(* Logix 5000 project; controller AMCI_3601_AOP_AOI_Sample_RSLogix_V28 vendor 1 type 14 code 108 rev 28.11; software revision 28.00; part 4 of 4 *)

ADD_ON_INSTRUCTION AMCI_3601_AOP_Relative_Move   (* revision 0.0, vendor AMCI, ExecuteEnableInFalse *)
// Revision note:
// 3/2020: Version 0 is the initial release
VAR_INPUT
   Axis_Status_Bits : INT; {required}
   _0_normal_1_S_Curve_Acceleration : BOOL;
   _0_Triangular_1_Trapezoidal_S_Curve : BOOL;
   _0_Target_Move_1_Encoder_Move : BOOL;
   Target_Position : DINT; {required}
   Programmed_Speed : DINT; {required}
   Acceleration : INT; {required}
   Deceleration : INT; {required}
END_VAR
VAR_OUTPUT
   EN : BOOL; {access Read Only, visible}
   ER : BOOL; {access Read Only, visible}
END_VAR
VAR_IN_OUT
   AMCI_3601_output_data : AM:1769_3601:O:0; {required}
END_VAR
VAR
   Upper_Result_X_1000 : DINT;
   command_data_block : INT[10];
        [1]   // Command Bits LSW
        [3]   // Lower Target Position
        [5]   // Lower Programmed Speed
        [0]   // Command Bits MSW
        [2]   // Upper Target Position
        [4]   // Upper Programmed Speed
END_VAR

ROUTINE EnableInFalse   (* ladder *)
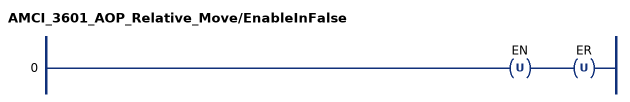
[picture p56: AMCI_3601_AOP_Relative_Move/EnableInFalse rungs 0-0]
   0: OTU(EN)OTU(ER);
END_ROUTINE

ROUTINE Logic   (* ladder *)
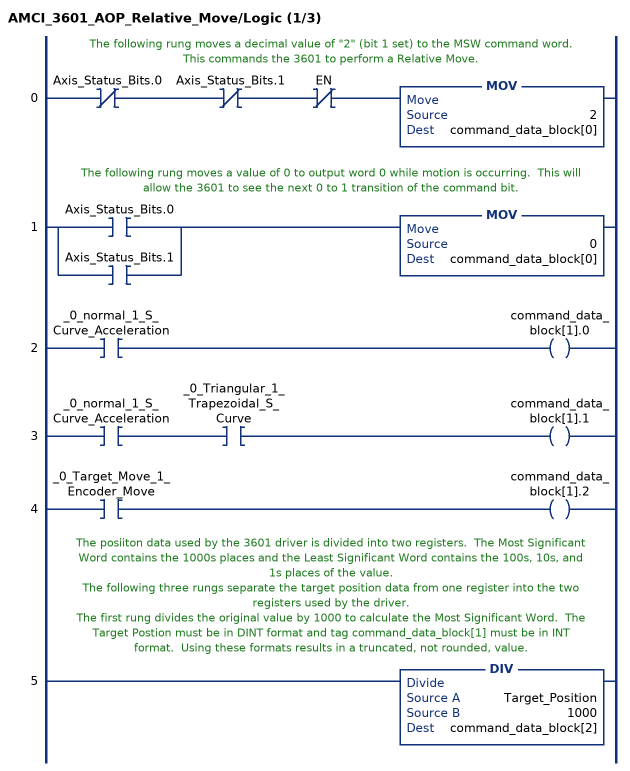
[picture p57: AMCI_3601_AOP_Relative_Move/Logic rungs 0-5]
   // The following rung moves a decimal value of "2" (bit 1 set) to the MSW command word.  This commands the 3601 to perform a Relative Move.
   0: XIO(Axis_Status_Bits.0)XIO(Axis_Status_Bits.1)XIO(EN)MOV(2,command_data_block[0]);
   // The following rung moves a value of 0 to output word 0 while motion is occurring.  This will allow the 3601 to see the next 0 to 1 transition of the command bit.
   1: [XIC(Axis_Status_Bits.0) ,XIC(Axis_Status_Bits.1) ]MOV(0,command_data_block[0]);
   2: XIC(_0_normal_1_S_Curve_Acceleration)OTE(command_data_block[1].0);
   3: XIC(_0_normal_1_S_Curve_Acceleration)XIC(_0_Triangular_1_Trapezoidal_S_Curve)OTE(command_data_block[1].1);
   4: XIC(_0_Target_Move_1_Encoder_Move)OTE(command_data_block[1].2);
   // The posiiton data used by the 3601 driver is divided into two registers.  The Most Significant Word contains the 1000s places and the Least Significant Word contains the 100s, 10s, and 1s places of the value.
   // The following three rungs separate the target position data from one register into the two registers used by the driver.
   // The first rung divides the original value by 1000 to calculate the Most Significant Word.  The Target Postion must be in DINT format and tag command_data_block[1] must be in INT format.  Using these formats results in a truncated, not rounded, value.
   5: DIV(Target_Position,1000,command_data_block[2]);
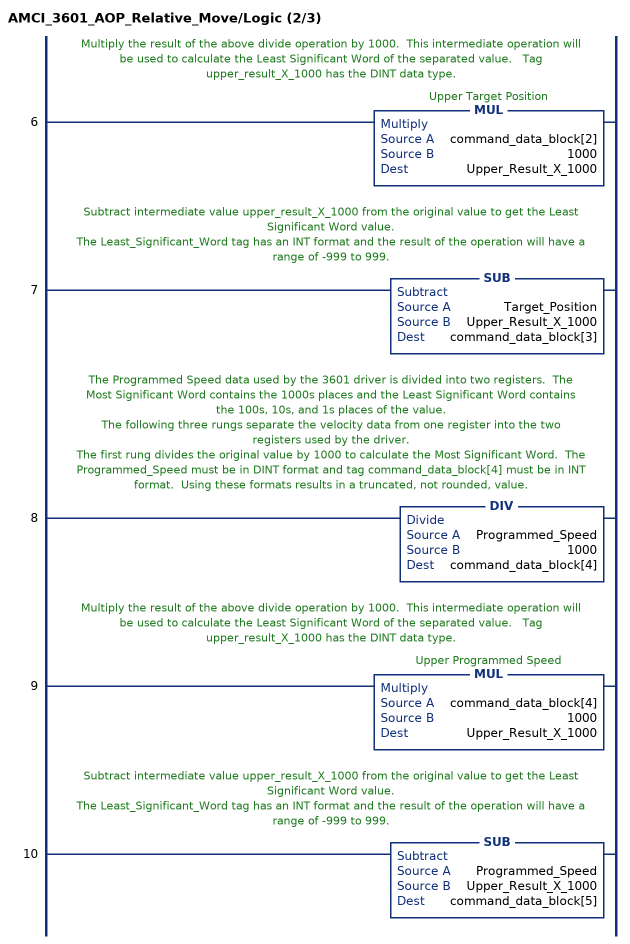
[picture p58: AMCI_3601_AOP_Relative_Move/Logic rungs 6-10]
   // Multiply the result of the above divide operation by 1000.  This intermediate operation will be used to calculate the Least Significant Word of the separated value.   Tag upper_result_X_1000 has the DINT data type.
   6: MUL(command_data_block[2],1000,Upper_Result_X_1000);
   // Subtract intermediate value upper_result_X_1000 from the original value to get the Least Significant Word value.
   // The Least_Significant_Word tag has an INT format and the result of the operation will have a range of -999 to 999.
   7: SUB(Target_Position,Upper_Result_X_1000,command_data_block[3]);
   // The Programmed Speed data used by the 3601 driver is divided into two registers.  The Most Significant Word contains the 1000s places and the Least Significant Word contains the 100s, 10s, and 1s places of the value.
   // The following three rungs separate the velocity data from one register into the two registers used by the driver.
   // The first rung divides the original value by 1000 to calculate the Most Significant Word.  The Programmed_Speed must be in DINT format and tag command_data_block[4] must be in INT format.  Using these formats results in a truncated, not rounded, value.
   8: DIV(Programmed_Speed,1000,command_data_block[4]);
   // Multiply the result of the above divide operation by 1000.  This intermediate operation will be used to calculate the Least Significant Word of the separated value.   Tag upper_result_X_1000 has the DINT data type.
   9: MUL(command_data_block[4],1000,Upper_Result_X_1000);
   // Subtract intermediate value upper_result_X_1000 from the original value to get the Least Significant Word value.
   // The Least_Significant_Word tag has an INT format and the result of the operation will have a range of -999 to 999.
   10: SUB(Programmed_Speed,Upper_Result_X_1000,command_data_block[5]);
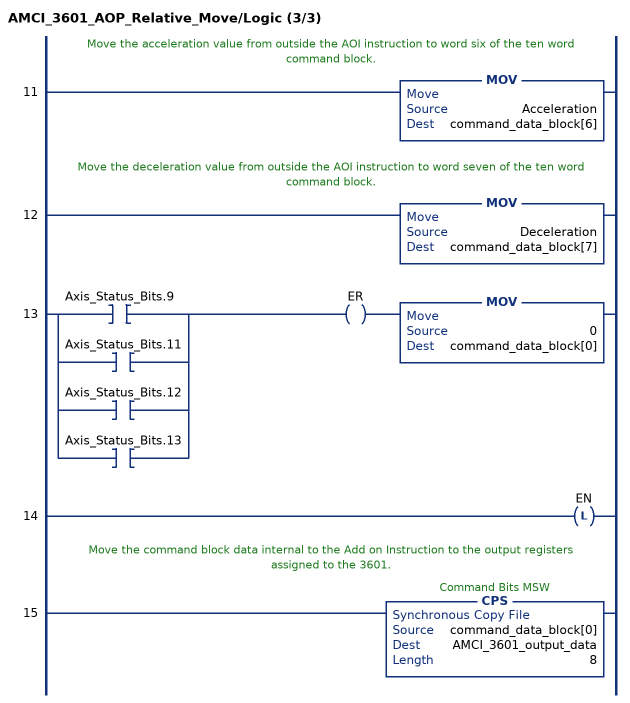
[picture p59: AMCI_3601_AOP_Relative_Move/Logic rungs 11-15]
   // Move the acceleration value from outside the AOI instruction to word six of the ten word command block.
   11: MOV(Acceleration,command_data_block[6]);
   // Move the deceleration value from outside the AOI instruction to word seven of the ten word command block.
   12: MOV(Deceleration,command_data_block[7]);
   13: [XIC(Axis_Status_Bits.9) ,XIC(Axis_Status_Bits.11) ,XIC(Axis_Status_Bits.12) ,XIC(Axis_Status_Bits.13) ]OTE(ER)MOV(0,command_data_block[0]);
   14: OTL(EN);
   // Move the command block data internal to the Add on Instruction to the output registers assigned to the 3601.
   15: CPS(command_data_block[0],AMCI_3601_output_data,8);
END_ROUTINE
END_ADD_ON_INSTRUCTION

ADD_ON_INSTRUCTION AMCI_3601_AOP_Reset_Errors   (* revision 0.0, vendor AMCI, ExecuteEnableInFalse *)
// Revision note:
// 3/2020: Version 0 is the initial release
VAR_INPUT
   Axis_Status_Bits : INT; {required}
END_VAR
VAR_OUTPUT
   EN : BOOL; {access Read Only, visible}
   ER : BOOL; {access Read Only, visible}
END_VAR
VAR_IN_OUT
   AMCI_3601_output_data : AM:1769_3601:O:0; {required}
END_VAR
VAR
   Upper_Result_X_1000 : DINT;
   command_data_block : INT[10];
        [1]   // Command Bits LSW
        [3]   // Lower Target Position
        [5]   // Lower Programmed Speed
        [0]   // Command Bits MSW
        [2]   // Upper Target Position
        [4]   // Upper Programmed Speed
END_VAR

ROUTINE EnableInFalse   (* ladder *)
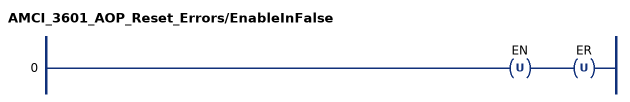
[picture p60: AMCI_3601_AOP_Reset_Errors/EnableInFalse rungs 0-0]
   0: OTU(EN)OTU(ER);
END_ROUTINE

ROUTINE Logic   (* ladder *)
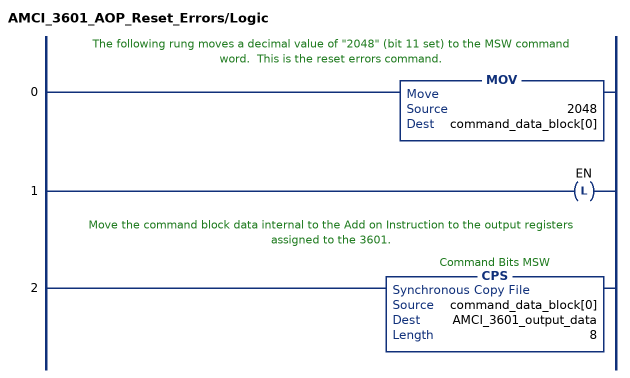
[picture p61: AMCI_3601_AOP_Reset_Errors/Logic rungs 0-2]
   // The following rung moves a decimal value of "2048" (bit 11 set) to the MSW command word.  This is the reset errors command.
   0: MOV(2048,command_data_block[0]);
   1: OTL(EN);
   // Move the command block data internal to the Add on Instruction to the output registers assigned to the 3601.
   2: CPS(command_data_block[0],AMCI_3601_output_data,8);
END_ROUTINE
END_ADD_ON_INSTRUCTION

ADD_ON_INSTRUCTION AMCI_3601_AOP_Resume   (* revision 0.0, vendor AMCI, ExecuteEnableInFalse *)
// Revision note:
// 3/2020: Version 0 is the initial release
VAR_INPUT
   Axis_Status_Bits : INT; {required}
END_VAR
VAR_OUTPUT
   EN : BOOL; {access Read Only, visible}
   ER : BOOL; {access Read Only, visible}
END_VAR
VAR_IN_OUT
   AMCI_3601_output_data : AM:1769_3601:O:0; {required}
END_VAR
VAR
   Upper_Result_X_1000 : DINT;
   command_data_block : INT[10];
        [1]   // Command Bits LSW
        [3]   // Lower Target Position
        [5]   // Lower Programmed Speed
        [0]   // Command Bits MSW
        [2]   // Upper Target Position
        [4]   // Upper Programmed Speed
END_VAR

ROUTINE EnableInFalse   (* ladder *)
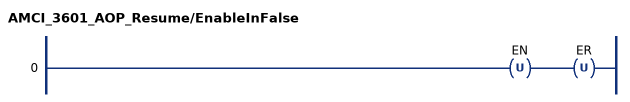
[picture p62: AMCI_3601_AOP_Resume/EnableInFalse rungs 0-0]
   0: OTU(EN)OTU(ER);
END_ROUTINE

ROUTINE Logic   (* ladder *)
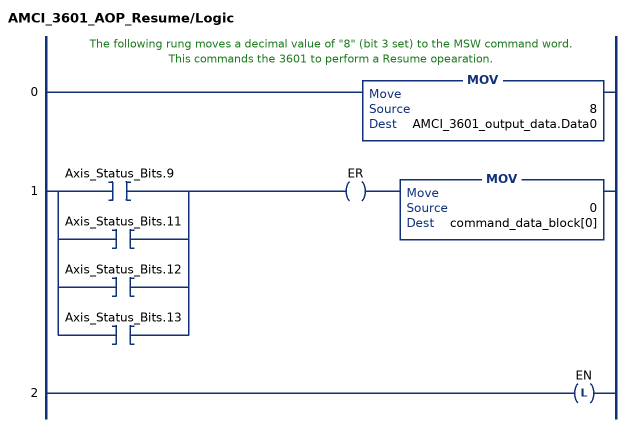
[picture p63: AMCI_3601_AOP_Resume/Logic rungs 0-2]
   // The following rung moves a decimal value of "8" (bit 3 set) to the MSW command word.  This commands the 3601 to perform a Resume opearation.
   0: MOV(8,AMCI_3601_output_data.Data0);
   1: [XIC(Axis_Status_Bits.9) ,XIC(Axis_Status_Bits.11) ,XIC(Axis_Status_Bits.12) ,XIC(Axis_Status_Bits.13) ]OTE(ER)MOV(0,command_data_block[0]);
   2: OTL(EN);
END_ROUTINE
END_ADD_ON_INSTRUCTION

ADD_ON_INSTRUCTION AMCI_3601_AOP_Run_Blend   (* revision 0.0, vendor AMCI, ExecuteEnableInFalse *)
// Revision note:
// 3/2020: Version 0 is the initial release
VAR_INPUT
   Axis_Status_Bits : INT; {required}
   Direction_0_Positive_1_Negative : BOOL; {required}
END_VAR
VAR_OUTPUT
   EN : BOOL; {access Read Only, visible}
   ER : BOOL; {access Read Only, visible}
END_VAR
VAR_IN_OUT
   AMCI_3601_output_data : AM:1769_3601:O:0; {required}
END_VAR
VAR
   Upper_Result_X_1000 : DINT;
   command_data_block : INT[10];
        [1]   // Command Bits LSW
        [3]   // Lower Target Position
        [5]   // Lower Programmed Speed
        [0]   // Command Bits MSW
        [2]   // Upper Target Position
        [4]   // Upper Programmed Speed
END_VAR

ROUTINE EnableInFalse   (* ladder *)
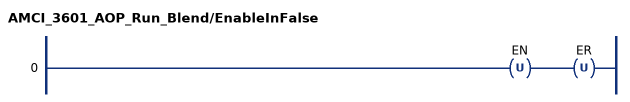
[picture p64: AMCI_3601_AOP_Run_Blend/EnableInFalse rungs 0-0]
   0: OTU(EN)OTU(ER);
END_ROUTINE

ROUTINE Logic   (* ladder *)
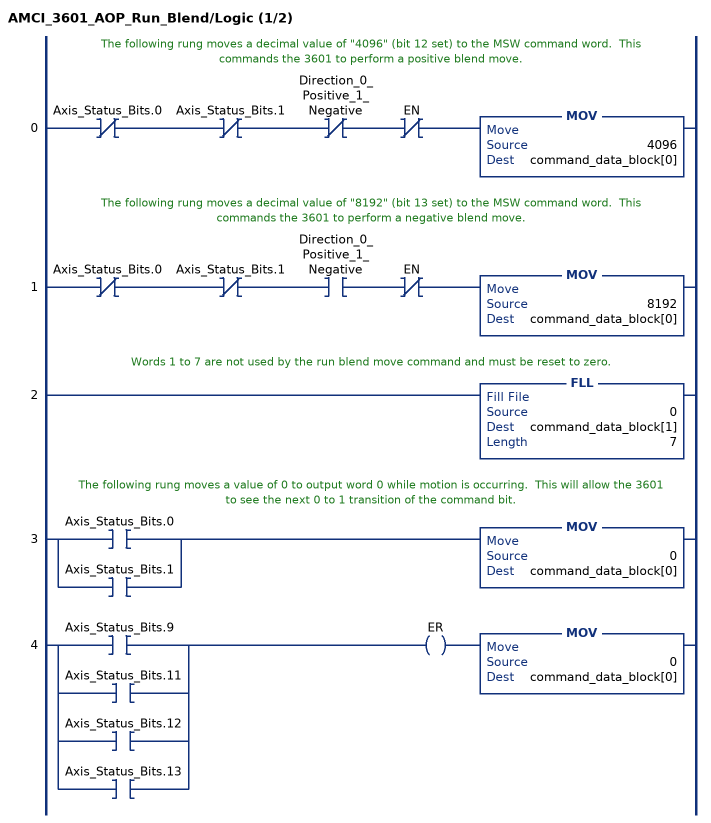
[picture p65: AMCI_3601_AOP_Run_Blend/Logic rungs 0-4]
   // The following rung moves a decimal value of "4096" (bit 12 set) to the MSW command word.  This commands the 3601 to perform a positive blend move.
   0: XIO(Axis_Status_Bits.0)XIO(Axis_Status_Bits.1)XIO(Direction_0_Positive_1_Negative)XIO(EN)MOV(4096,command_data_block[0]);
   // The following rung moves a decimal value of "8192" (bit 13 set) to the MSW command word.  This commands the 3601 to perform a negative blend move.
   1: XIO(Axis_Status_Bits.0)XIO(Axis_Status_Bits.1)XIC(Direction_0_Positive_1_Negative)XIO(EN)MOV(8192,command_data_block[0]);
   // Words 1 to 7 are not used by the run blend move command and must be reset to zero.
   2: FLL(0,command_data_block[1],7);
   // The following rung moves a value of 0 to output word 0 while motion is occurring.  This will allow the 3601 to see the next 0 to 1 transition of the command bit.
   3: [XIC(Axis_Status_Bits.0) ,XIC(Axis_Status_Bits.1) ]MOV(0,command_data_block[0]);
   4: [XIC(Axis_Status_Bits.9) ,XIC(Axis_Status_Bits.11) ,XIC(Axis_Status_Bits.12) ,XIC(Axis_Status_Bits.13) ]OTE(ER)MOV(0,command_data_block[0]);
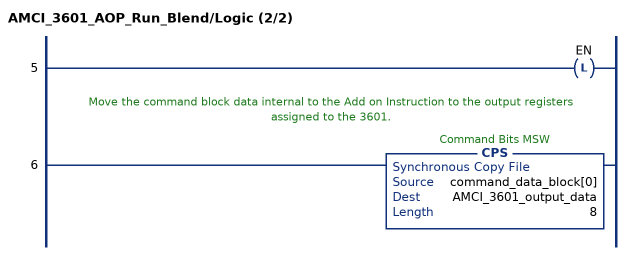
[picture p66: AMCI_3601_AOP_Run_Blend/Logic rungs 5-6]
   5: OTL(EN);
   // Move the command block data internal to the Add on Instruction to the output registers assigned to the 3601.
   6: CPS(command_data_block[0],AMCI_3601_output_data,8);
END_ROUTINE
END_ADD_ON_INSTRUCTION

VAR_GLOBAL   (* controller tags *)
   buffered_3601_data : INT[8];
        [0].13   // set when configuration error
        [0].15   // 3601 mode 0=command 1=configuration
   comment_coil : INT;
   run_3601 : DINT;   // 1=relative move 2=CW Manual Move 3=CCW Manual Move 4=Home CW 5=Reset Errors 6=Preset 7=Program Blend 8=Run Blend
END_VAR

PROGRAM MainProgram   (* main routine MainRoutine *)
VAR
   AMCI_3601_absolute_move_AOI : AMCI_3601_AOP_Absolute_Move;
   AMCI_3601_Config_AOI : AMCI_3601_AOP_Configure;
   AMCI_3601_encoder_follower_AOI : AMCI_3601_AOP_Encoder_Follower;
   AMCI_3601_Hold_AOI : AMCI_3601_AOP_Hold;
   AMCI_3601_Home_CCW_AOI : AMCI_3601_AOP_Home_CCW;
   AMCI_3601_Home_CW_AOI : AMCI_3601_AOP_Home_CW;
   AMCI_3601_Immediate_Stop_AOI : AMCI_3601_AOP_Immediate_Stop;
   AMCI_3601_Manual_Move_CCW_AOI : AMCI_3601_AOP_Manual_Move_CCW;
   AMCi_3601_Manual_Move_CW_AOI : AMCI_3601_AOP_Manual_Move_CW;
   AMCI_3601_Preset_AOI : AMCI_3601_AOP_Preset;
   AMCI_3601_Preset_Encoder_AOI : AMCI_3601_AOP_Preset_Encoder;
   AMCI_3601_program_blend_AOI : AMCI_3601_AOP_Program_Blend_Move;
   AMCI_3601_Registration_CCW : AMCI_3601_AOP_Registration_CCW;
   AMCI_3601_Registration_CW_AOI : AMCI_3601_AOP_Registration_CW;
   AMCI_3601_Relative_Move_AOI : AMCI_3601_AOP_Relative_Move;
   AMCI_3601_Reset_Error_AOI : AMCI_3601_AOP_Reset_Errors;
   AMCI_3601_Resume_AOI : AMCI_3601_AOP_Resume;
   AMCI_3601_run_blend_AOI : AMCI_3601_AOP_Run_Blend;
   AMCI_Prog_Min_Registration_Distance_AOI : AMCI_3601_AOP_Min_Registration_Distance;
END_VAR

ROUTINE MainRoutine   (* ladder *)
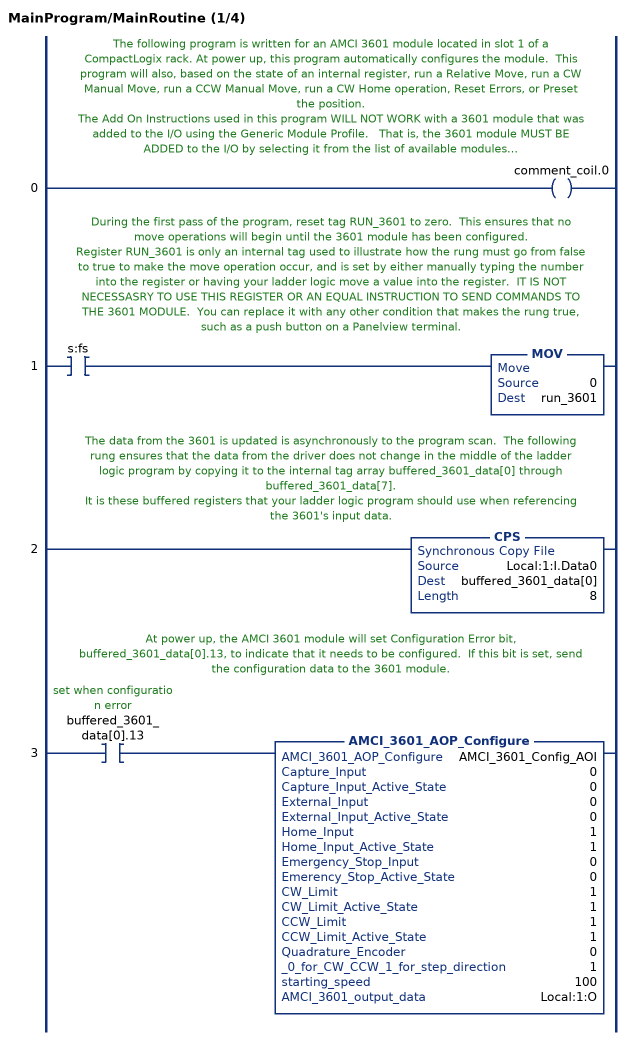
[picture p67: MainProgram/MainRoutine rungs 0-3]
   // The following program is written for an AMCI 3601 module located in slot 1 of a CompactLogix rack. At power up, this program automatically configures the module.  This program will also, based on the state of an internal register, run a Relative Move, run a CW Manual Move, run a CCW Manual Move, run a CW Home operation, Reset Errors, or Preset the position.
   // The Add On Instructions used in this program WILL NOT WORK with a 3601 module that was added to the I/O using the Generic Module Profile.   That is, the 3601 module MUST BE ADDED to the I/O by selecting it from the list of available modules.
   // The Add On Instructions have some of the 3601’s lesser used functions, such as S Curve Acceleration, hidden.  The Add On Instructions are not locked or protected and, if desired, these functions can be enabled and made visible.
   // Subroutine Program_Run_Blend shows how to program and run a Blend Move Profile.  This subroutine is optional and can be ignored or deleted.
   // Register RUN_3601 is only an internal tag used to illustrate how the rung must go from false to true to make the move operation occur, and is set by either manually typing the number into the register or having your ladder logic move a value into the register.  IT IS NOT NECESSASRY TO USE THIS REGISTER OR AN EQUAL INSTRUCTION TO SEND COMMANDS TO THE 3601 MODULE.  You can replace it with any other condition that makes the rung true, such as a push button on a Panelview terminal.
   0: OTE(comment_coil.0);
   // During the first pass of the program, reset tag RUN_3601 to zero.  This ensures that no move operations will begin until the 3601 module has been configured.
   // Register RUN_3601 is only an internal tag used to illustrate how the rung must go from false to true to make the move operation occur, and is set by either manually typing the number into the register or having your ladder logic move a value into the register.  IT IS NOT NECESSASRY TO USE THIS REGISTER OR AN EQUAL INSTRUCTION TO SEND COMMANDS TO THE 3601 MODULE.  You can replace it with any other condition that makes the rung true, such as a push button on a Panelview terminal.
   1: XIC(s:fs)MOV(0,run_3601);
   // The data from the 3601 is updated is asynchronously to the program scan.  The following rung ensures that the data from the driver does not change in the middle of the ladder logic program by copying it to the internal tag array buffered_3601_data[0] through buffered_3601_data[7].
   // It is these buffered registers that your ladder logic program should use when referencing the 3601's input data.
   2: CPS(Local:1:I.Data0,buffered_3601_data[0],8);
   // At power up, the AMCI 3601 module will set Configuration Error bit, buffered_3601_data[0].13, to indicate that it needs to be configured.  If this bit is set, send the configuration data to the 3601 module.
   3: XIC(buffered_3601_data[0].13)AMCI_3601_AOP_Configure(AMCI_3601_Config_AOI,0,0,0,0,1,1,0,0,1,1,1,1,0,1,100,Local:1:O);
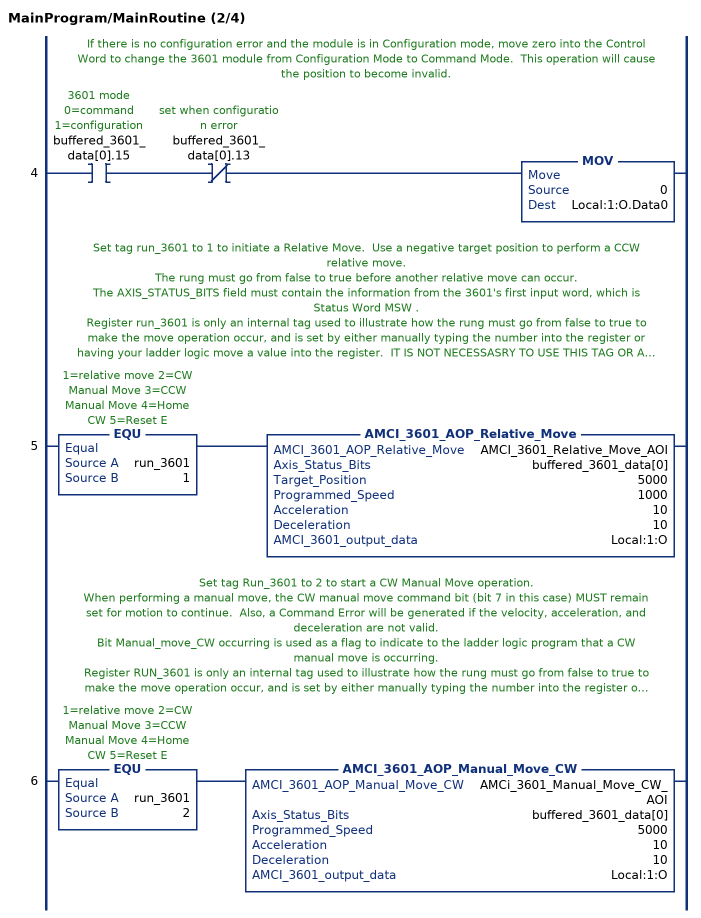
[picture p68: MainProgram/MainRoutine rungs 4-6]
   // If there is no configuration error and the module is in Configuration mode, move zero into the Control Word to change the 3601 module from Configuration Mode to Command Mode.  This operation will cause the position to become invalid.
   4: XIC(buffered_3601_data[0].15)XIO(buffered_3601_data[0].13)MOV(0,Local:1:O.Data0);
   // Set tag run_3601 to 1 to initiate a Relative Move.  Use a negative target position to perform a CCW relative move.
   // The rung must go from false to true before another relative move can occur.
   // The AXIS_STATUS_BITS field must contain the information from the 3601's first input word, which is Status Word MSW .
   // Register run_3601 is only an internal tag used to illustrate how the rung must go from false to true to make the move operation occur, and is set by either manually typing the number into the register or having your ladder logic move a value into the register.  IT IS NOT NECESSASRY TO USE THIS TAG OR AN EQUAL INSTRUCTION TO SEND COMMANDS TO THE AMCI 3601.  You can replace it with any other condition that makes the rung true, such as a push button on a HMI terminal.
   5: EQU(run_3601,1)AMCI_3601_AOP_Relative_Move(AMCI_3601_Relative_Move_AOI,buffered_3601_data[0],5000,1000,10,10,Local:1:O);
   // Set tag Run_3601 to 2 to start a CW Manual Move operation.
   // When performing a manual move, the CW manual move command bit (bit 7 in this case) MUST remain set for motion to continue.  Also, a Command Error will be generated if the velocity, acceleration, and deceleration are not valid.
   // Bit Manual_move_CW occurring is used as a flag to indicate to the ladder logic program that a CW manual move is occurring.
   // Register RUN_3601 is only an internal tag used to illustrate how the rung must go from false to true to make the move operation occur, and is set by either manually typing the number into the register or having your ladder logic move a value into the register.  IT IS NOT NECESSASRY TO USE THIS REGISTER OR AN EQUAL INSTRUCTION TO SEND COMMANDS TO THE 3601 MODULE.  You can replace it with any other condition that makes the rung true, such as a push button on a Panelview terminal.
   6: EQU(run_3601,2)AMCI_3601_AOP_Manual_Move_CW(AMCi_3601_Manual_Move_CW_AOI,buffered_3601_data[0],5000,10,10,Local:1:O);
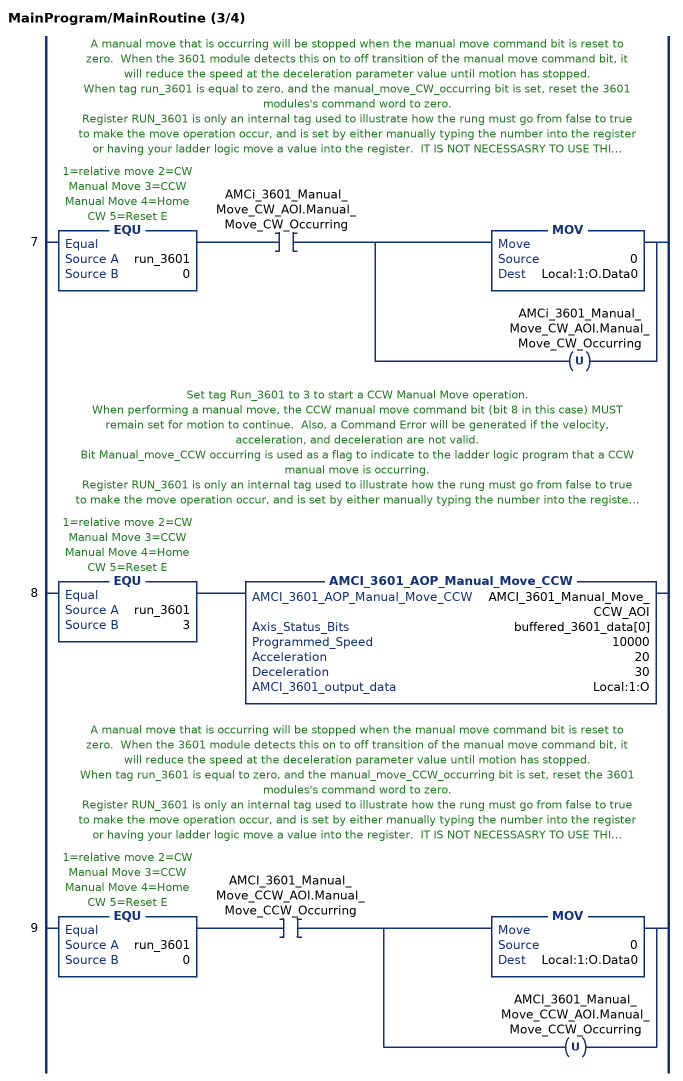
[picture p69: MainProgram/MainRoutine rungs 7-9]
   // A manual move that is occurring will be stopped when the manual move command bit is reset to zero.  When the 3601 module detects this on to off transition of the manual move command bit, it will reduce the speed at the deceleration parameter value until motion has stopped.
   // When tag run_3601 is equal to zero, and the manual_move_CW_occurring bit is set, reset the 3601 modules's command word to zero.
   // Register RUN_3601 is only an internal tag used to illustrate how the rung must go from false to true to make the move operation occur, and is set by either manually typing the number into the register or having your ladder logic move a value into the register.  IT IS NOT NECESSASRY TO USE THIS REGISTER OR AN EQUAL INSTRUCTION TO SEND COMMANDS TO THE 3601 MODULE.  You can replace it with any other condition that makes the rung true, such as a push button on a Panelview terminal.
   7: EQU(run_3601,0)XIC(AMCi_3601_Manual_Move_CW_AOI.Manual_Move_CW_Occurring)[MOV(0,Local:1:O.Data0) ,OTU(AMCi_3601_Manual_Move_CW_AOI.Manual_Move_CW_Occurring) ];
   // Set tag Run_3601 to 3 to start a CCW Manual Move operation.
   // When performing a manual move, the CCW manual move command bit (bit 8 in this case) MUST remain set for motion to continue.  Also, a Command Error will be generated if the velocity, acceleration, and deceleration are not valid.
   // Bit Manual_move_CCW occurring is used as a flag to indicate to the ladder logic program that a CCW manual move is occurring.
   // Register RUN_3601 is only an internal tag used to illustrate how the rung must go from false to true to make the move operation occur, and is set by either manually typing the number into the register or having your ladder logic move a value into the register.  IT IS NOT NECESSASRY TO USE THIS REGISTER OR AN EQUAL INSTRUCTION TO SEND COMMANDS TO THE 3601 MODULE.  You can replace it with any other condition that makes the rung true, such as a push button on a Panelview terminal.
   8: EQU(run_3601,3)AMCI_3601_AOP_Manual_Move_CCW(AMCI_3601_Manual_Move_CCW_AOI,buffered_3601_data[0],10000,20,30,Local:1:O);
   // A manual move that is occurring will be stopped when the manual move command bit is reset to zero.  When the 3601 module detects this on to off transition of the manual move command bit, it will reduce the speed at the deceleration parameter value until motion has stopped.
   // When tag run_3601 is equal to zero, and the manual_move_CCW_occurring bit is set, reset the 3601 modules's command word to zero.
   // Register RUN_3601 is only an internal tag used to illustrate how the rung must go from false to true to make the move operation occur, and is set by either manually typing the number into the register or having your ladder logic move a value into the register.  IT IS NOT NECESSASRY TO USE THIS REGISTER OR AN EQUAL INSTRUCTION TO SEND COMMANDS TO THE 3601 MODULE.  You can replace it with any other condition that makes the rung true, such as a push button on a Panelview terminal.
   9: EQU(run_3601,0)XIC(AMCI_3601_Manual_Move_CCW_AOI.Manual_Move_CCW_Occurring)[MOV(0,Local:1:O.Data0) ,OTU(AMCI_3601_Manual_Move_CCW_AOI.Manual_Move_CCW_Occurring) ];
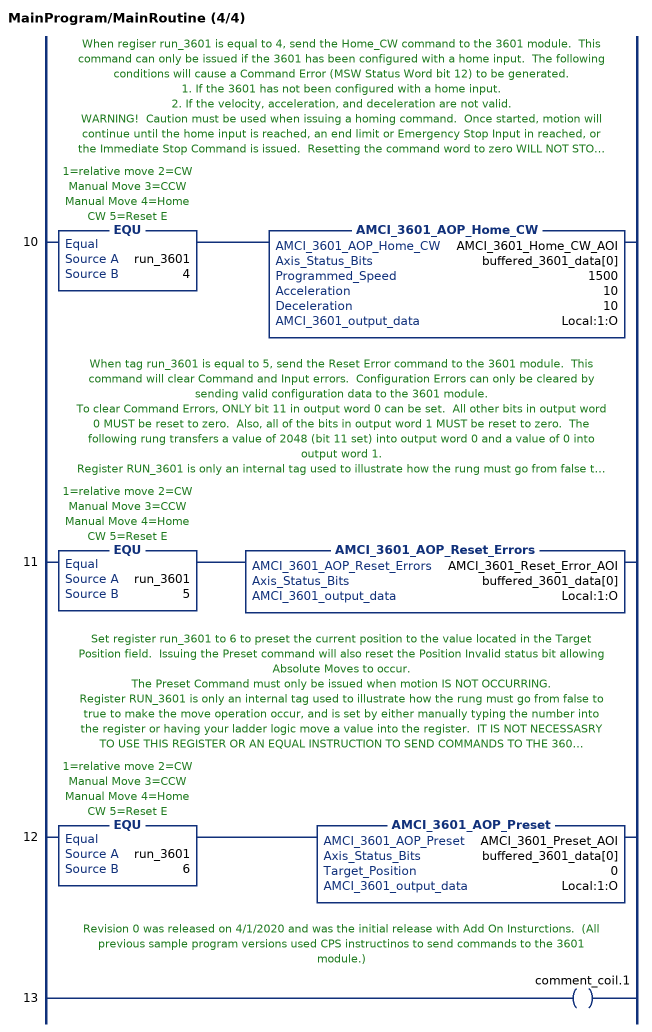
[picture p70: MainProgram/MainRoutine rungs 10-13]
   // When regiser run_3601 is equal to 4, send the Home_CW command to the 3601 module.  This command can only be issued if the 3601 has been configured with a home input.  The following conditions will cause a Command Error (MSW Status Word bit 12) to be generated.
   // 1. If the 3601 has not been configured with a home input.
   // 2. If the velocity, acceleration, and deceleration are not valid.
   // WARNING!  Caution must be used when issuing a homing command.  Once started, motion will continue until the home input is reached, an end limit or Emergency Stop Input in reached, or the Immediate Stop Command is issued.  Resetting the command word to zero WILL NOT STOP a home operation.
   // Register RUN_3601 is only an internal tag used to illustrate how the rung must go from false to true to make the move operation occur, and is set by either manually typing the number into the register or having your ladder logic move a value into the register.  IT IS NOT NECESSASRY TO USE THIS REGISTER OR AN EQUAL INSTRUCTION TO SEND COMMANDS TO THE 3601 MODULE.  You can replace it with any other condition that makes the rung true, such as a push button on a Panelview terminal.
   10: EQU(run_3601,4)AMCI_3601_AOP_Home_CW(AMCI_3601_Home_CW_AOI,buffered_3601_data[0],1500,10,10,Local:1:O);
   // When tag run_3601 is equal to 5, send the Reset Error command to the 3601 module.  This command will clear Command and Input errors.  Configuration Errors can only be cleared by sending valid configuration data to the 3601 module.
   // To clear Command Errors, ONLY bit 11 in output word 0 can be set.  All other bits in output word 0 MUST be reset to zero.  Also, all of the bits in output word 1 MUST be reset to zero.  The following rung transfers a value of 2048 (bit 11 set) into output word 0 and a value of 0 into output word 1.
   // Register RUN_3601 is only an internal tag used to illustrate how the rung must go from false to true to make the move operation occur, and is set by either manually typing the number into the register or having your ladder logic move a value into the register.  IT IS NOT NECESSASRY TO USE THIS REGISTER OR AN EQUAL INSTRUCTION TO SEND COMMANDS TO THE 3601 MODULE.  You can replace it with any other condition that makes the rung true, such as a push button on a Panelview terminal.
   11: EQU(run_3601,5)AMCI_3601_AOP_Reset_Errors(AMCI_3601_Reset_Error_AOI,buffered_3601_data[0],Local:1:O);
   // Set register run_3601 to 6 to preset the current position to the value located in the Target Position field.  Issuing the Preset command will also reset the Position Invalid status bit allowing Absolute Moves to occur.
   // The Preset Command must only be issued when motion IS NOT OCCURRING.
   // Register RUN_3601 is only an internal tag used to illustrate how the rung must go from false to true to make the move operation occur, and is set by either manually typing the number into the register or having your ladder logic move a value into the register.  IT IS NOT NECESSASRY TO USE THIS REGISTER OR AN EQUAL INSTRUCTION TO SEND COMMANDS TO THE 3601 MODULE.  You can replace it with any other condition that makes the rung true, such as a push button on a Panelview terminal.
   12: EQU(run_3601,6)AMCI_3601_AOP_Preset(AMCI_3601_Preset_AOI,buffered_3601_data[0],0,Local:1:O);
   // Revision 0 was released on 4/1/2020 and was the initial release with Add On Insturctions.  (All previous sample program versions used CPS instructinos to send commands to the 3601 module.)
   13: OTE(comment_coil.1);
END_ROUTINE

ROUTINE Program_Run_Blend   (* ladder *)
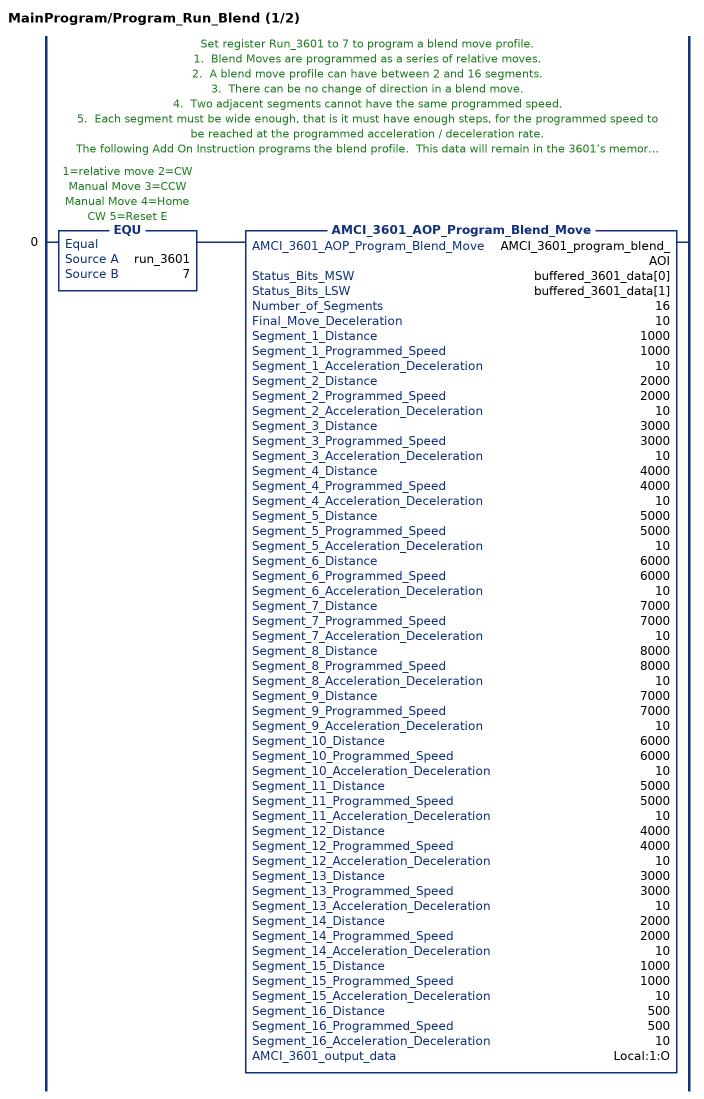
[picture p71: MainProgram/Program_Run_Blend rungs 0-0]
   // Set register Run_3601 to 7 to program a blend move profile.
   // 1.	Blend Moves are programmed as a series of relative moves.
   // 2.	A blend move profile can have between 2 and 16 segments.
   // 3.	There can be no change of direction in a blend move.
   // 4.	Two adjacent segments cannot have the same programmed speed.
   // 5.	Each segment must be wide enough, that is it must have enough steps, for the programmed speed to be reached at the programmed acceleration / deceleration rate.
   // The following Add On Instruction programs the blend profile.  This data will remain in the 3601’s memory until you cycle power, if you program the configuration data, or if you program a new blend profile.
   // The saved blend profile can be run multiple times, in either direction, using the Run_Blend_Move AOI also shown in this subroutine.
   // Register RUN_3601 is only an internal tag used to illustrate how the rung must go from false to true to make the move operation occur, and is set by either manually typing the number into the register or having your ladder logic move a value into the register.  IT IS NOT NECESSASRY TO USE THIS REGISTER OR AN EQUAL INSTRUCTION TO SEND COMMANDS TO THE 3601 MODULE.  You can replace it with any other condition that makes the rung true, such as a push button on a Panelview terminal.
   0: EQU(run_3601,7)AMCI_3601_AOP_Program_Blend_Move(AMCI_3601_program_blend_AOI,buffered_3601_data[0],buffered_3601_data[1],16,10,1000,1000,10,2000,2000,10,3000,3000,10,4000,4000,10,5000,5000,10,6000,6000,10,7000,7000,10,8000,8000,10,7000,7000,10,6000,6000,10,5000,5000,10,4000,4000,10,3000,3000,10,2000,2000,10,1000,1000,10,500,500,10,Local:1:O);
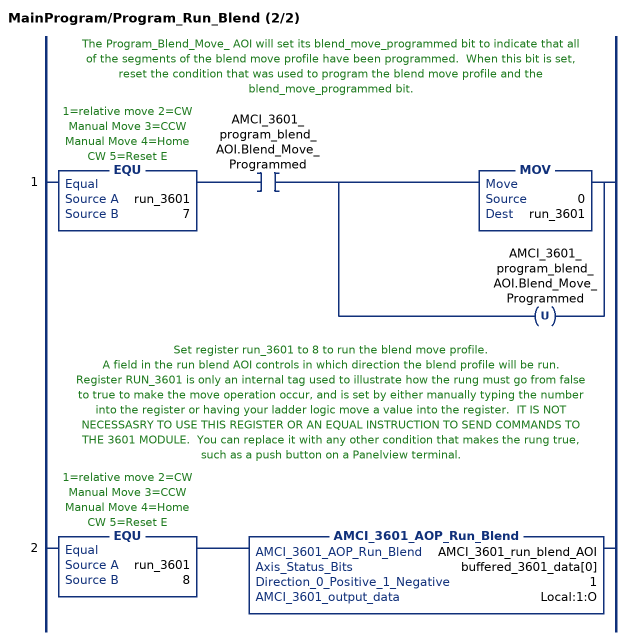
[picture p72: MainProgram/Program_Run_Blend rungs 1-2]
   // The Program_Blend_Move_ AOI will set its blend_move_programmed bit to indicate that all of the segments of the blend move profile have been programmed.  When this bit is set, reset the condition that was used to program the blend move profile and the blend_move_programmed bit.
   1: EQU(run_3601,7)XIC(AMCI_3601_program_blend_AOI.Blend_Move_Programmed)[MOV(0,run_3601) ,OTU(AMCI_3601_program_blend_AOI.Blend_Move_Programmed) ];
   // Set register run_3601 to 8 to run the blend move profile.
   // A field in the run blend AOI controls in which direction the blend profile will be run.
   // Register RUN_3601 is only an internal tag used to illustrate how the rung must go from false to true to make the move operation occur, and is set by either manually typing the number into the register or having your ladder logic move a value into the register.  IT IS NOT NECESSASRY TO USE THIS REGISTER OR AN EQUAL INSTRUCTION TO SEND COMMANDS TO THE 3601 MODULE.  You can replace it with any other condition that makes the rung true, such as a push button on a Panelview terminal.
   2: EQU(run_3601,8)AMCI_3601_AOP_Run_Blend(AMCI_3601_run_blend_AOI,buffered_3601_data[0],1,Local:1:O);
END_ROUTINE
END_PROGRAM
